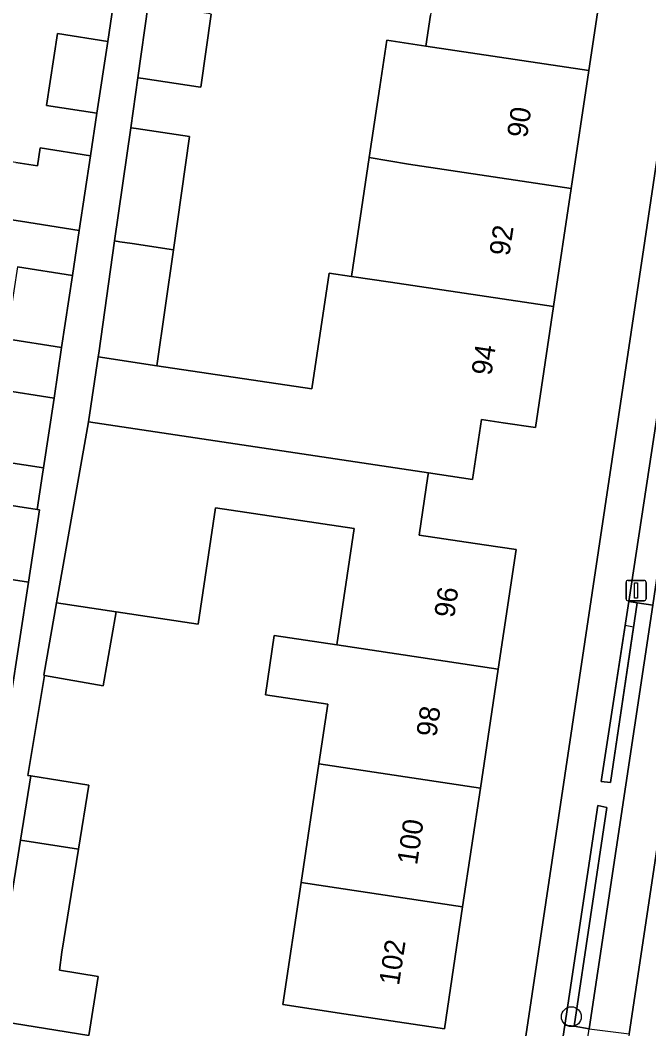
# Model space of a CAD drawing. Extents: x 163008 to 163854, y 382777 to 383982.
# Drawn here: x 163310.89 to 163341.84, y 383111.34 to 383160.98 of the extents above; entities that cross this region are included whole.
import ezdxf

# ---------------------------------------------------------------- set-up
doc = ezdxf.new("R2010")
doc.units = 0
for name, color, linetype in [('IMGEO_Boom', 7, 'Continuous'), ('IMGEO_Erf', 7, 'Continuous'), ('IMGEO_Groenvoorziening', 7, 'Continuous'), ('IMGEO_Haag', 7, 'Continuous'), ('IMGEO_Lichtmast', 7, 'Continuous'), ('IMGEO_Pand', 7, 'Continuous'), ('IMGEO_Pand_nummerreeks', 7, 'Continuous'), ('IMGEO_Parkeervlak_open', 7, 'Continuous'), ('IMGEO_Rijbaan_lokaal_gesloten', 7, 'Continuous'), ('IMGEO_Voetpad_open', 7, 'Continuous')]:
    doc.layers.add(name, color=color, linetype=linetype)

msp = doc.modelspace()

# ---------------------------------------------------------------- linework, layer by layer
at = {"layer": 'IMGEO_Boom'}
msp.add_circle((163338.027, 383111.934), 0.489, dxfattribs=at)
at = {"layer": 'IMGEO_Erf'}
for points in [[(163310.677, 383153.971), (163311.748, 383153.81), (163311.882, 383154.698), (163314.358, 383154.309), (163314.673, 383156.4), (163312.197, 383156.789), (163312.729, 383160.32), (163315.205, 383159.932), (163315.542, 383162.168), (163313.066, 383162.556), (163313.602, 383166.112), (163316.078, 383165.723), (163316.411, 383167.934), (163313.935, 383168.323), (163314.469, 383171.872), (163316.948, 383171.499), (163317.457, 383174.88), (163313.908, 383175.415), (163294.265, 383178.498)], [(163325.006, 383038.94), (163341.637, 383150.129), (163344.666, 383170.44)], [(163339.761, 383164.312), (163338.89, 383158.502), (163338.019, 383152.692), (163337.149, 383146.882), (163336.256, 383140.926), (163334.674, 383141.163), (163333.596, 383141.324), (163333.154, 383138.372), (163330.989, 383138.697), (163330.966, 383138.545), (163330.531, 383135.638), (163333.728, 383135.16), (163335.31, 383134.923), (163334.427, 383129.034), (163333.551, 383123.185), (163332.674, 383117.337), (163331.776, 383111.342), (163326.832, 383112.083), (163323.826, 383112.534), (163324.725, 383118.534), (163325.602, 383124.382), (163326.04, 383127.309), (163322.967, 383127.77), (163323.405, 383130.694), (163326.479, 383130.234), (163327.337, 383135.962), (163320.516, 383136.985), (163319.658, 383131.259), (163315.627, 383131.866), (163314.985, 383128.223), (163312.091, 383128.733), (163311.274, 383123.811), (163311.411, 383123.789), (163314.266, 383123.331), (163313.762, 383120.185), (163312.948, 383115.114), (163312.829, 383114.22), (163314.739, 383113.914), (163314.273, 383111.005), (163309.485, 383111.773)], [(163320.3, 383161.284), (163319.788, 383157.679), (163319.65, 383157.7), (163316.947, 383158.104), (163316.684, 383158.143), (163316.335, 383155.689), (163316.599, 383155.65), (163319.231, 383155.256), (163318.438, 383149.683), (163317.626, 383143.976), (163325.249, 383142.834), (163326.103, 383148.531), (163327.197, 383148.369), (163328.073, 383154.217), (163328.596, 383157.709), (163328.938, 383159.991), (163330.856, 383159.704), (163331.085, 383161.233)], [(163310.756, 383148.838), (163313.47, 383148.413), (163313.805, 383150.636), (163310.916, 383151.089), (163310.259, 383151.192)], [(163309.847, 383142.806), (163312.561, 383142.381), (163312.936, 383144.869), (163310.222, 383145.295)], [(163308.864, 383137.335), (163311.73, 383136.896), (163311.996, 383138.634), (163312.044, 383138.954), (163309.328, 383139.364)]]:
    msp.add_lwpolyline(points, dxfattribs=at)
at = {"layer": 'IMGEO_Groenvoorziening'}
for points in [[(163341.271, 383132.306), (163340.86, 383132.369), (163339.502, 383123.514), (163339.948, 383123.467)], [(163339.778, 383122.237), (163339.334, 383122.331), (163337.704, 383111.517), (163338.168, 383111.467)]]:
    msp.add_lwpolyline(points, close=True, dxfattribs=at)
at = {"layer": 'IMGEO_Haag'}
for points in [[(163341.091, 383131.106), (163340.678, 383131.182), (163339.502, 383123.514), (163339.948, 383123.467)], [(163339.778, 383122.237), (163339.334, 383122.331), (163337.704, 383111.517), (163338.168, 383111.467)]]:
    msp.add_lwpolyline(points, close=True, dxfattribs=at)
at = {"layer": 'IMGEO_Lichtmast'}
for p, q in [((163340.717, 383132.509), (163340.717, 383133.309)), ((163340.717, 383133.309), (163340.717, 383132.509)), ((163340.817, 383133.409), (163341.607, 383133.409)), ((163341.607, 383133.409), (163340.817, 383133.409)), ((163341.707, 383133.309), (163341.707, 383132.509)), ((163341.707, 383132.509), (163341.707, 383133.309)), ((163341.607, 383132.409), (163340.817, 383132.409)), ((163340.817, 383132.409), (163341.607, 383132.409))]:
    msp.add_line(p, q, dxfattribs=at)
msp.add_lwpolyline([(163341.137, 383133.284), (163341.287, 383133.284), (163341.287, 383132.534), (163341.137, 383132.534), (163341.137, 383133.284)], dxfattribs=at)
for centre, start, end in [((163340.817, 383133.309), 90, 180), ((163340.817, 383133.309), 90, 180), ((163341.607, 383133.309), 0, 90), ((163341.607, 383133.309), 360, 90), ((163340.817, 383132.509), 180, 270), ((163340.817, 383132.509), 180, 270), ((163341.607, 383132.509), 270, 0), ((163341.607, 383132.509), 270, 0)]:
    msp.add_arc(centre, 0.1, start, end, dxfattribs=at)
at = {"layer": 'IMGEO_Pand'}
for points in [[(163339.761, 383164.312), (163331.726, 383165.514), (163331.713, 383165.425), (163331.35, 383163), (163331.085, 383161.233), (163330.856, 383159.704), (163338.89, 383158.502)], [(163320.3, 383161.284), (163320.162, 383161.304), (163317.808, 383161.657), (163317.46, 383161.709), (163317.196, 383161.749), (163316.684, 383158.143), (163316.947, 383158.104), (163319.65, 383157.7), (163319.788, 383157.679)], [(163315.205, 383159.932), (163312.729, 383160.32), (163312.197, 383156.789), (163314.673, 383156.4)], [(163338.89, 383158.502), (163330.856, 383159.704), (163328.938, 383159.991), (163328.596, 383157.709), (163328.073, 383154.217), (163330.006, 383153.891), (163338.019, 383152.692)], [(163316.335, 383155.689), (163315.542, 383150.115), (163315.806, 383150.076), (163316.406, 383149.986), (163318.438, 383149.683), (163319.231, 383155.256), (163316.599, 383155.65)], [(163314.358, 383154.309), (163311.882, 383154.698), (163311.748, 383153.81), (163310.677, 383153.971), (163310.12, 383154.055), (163309.702, 383151.279), (163310.259, 383151.192), (163310.916, 383151.089), (163313.805, 383150.636)], [(163338.019, 383152.692), (163330.006, 383153.891), (163328.073, 383154.217), (163327.197, 383148.369), (163329.119, 383148.083), (163337.149, 383146.882)], [(163318.438, 383149.683), (163316.406, 383149.986), (163315.806, 383150.076), (163315.542, 383150.115), (163314.758, 383144.6), (163314.731, 383144.41), (163317.626, 383143.976)], [(163313.47, 383148.413), (163310.756, 383148.838), (163310.222, 383145.295), (163312.936, 383144.869)], [(163337.149, 383146.882), (163329.119, 383148.083), (163327.197, 383148.369), (163326.103, 383148.531), (163325.249, 383142.834), (163317.626, 383143.976), (163314.731, 383144.41), (163314.252, 383141.206), (163330.989, 383138.697), (163333.154, 383138.372), (163333.596, 383141.324), (163334.674, 383141.163), (163336.256, 383140.926)], [(163312.561, 383142.381), (163309.847, 383142.806), (163309.328, 383139.364), (163312.044, 383138.954)], [(163335.31, 383134.923), (163333.728, 383135.16), (163330.531, 383135.638), (163330.966, 383138.545), (163330.989, 383138.697), (163314.252, 383141.206), (163312.685, 383132.309), (163315.627, 383131.866), (163319.658, 383131.259), (163320.516, 383136.985), (163327.337, 383135.962), (163326.479, 383130.234), (163334.427, 383129.034)], [(163311.85, 383136.878), (163311.73, 383136.896), (163308.864, 383137.335), (163308.322, 383133.786), (163311.306, 383133.318)], [(163308.322, 383133.786), (163307.44, 383128.018), (163310.425, 383127.55), (163311.306, 383133.318)], [(163315.627, 383131.866), (163312.685, 383132.309), (163312.056, 383128.739), (163312.091, 383128.733), (163314.985, 383128.223)], [(163325.602, 383124.382), (163333.551, 383123.185), (163334.427, 383129.034), (163326.479, 383130.234), (163323.405, 383130.694), (163322.967, 383127.77), (163326.04, 383127.309)], [(163325.602, 383124.382), (163324.725, 383118.534), (163332.674, 383117.337), (163333.551, 383123.185)], [(163311.411, 383123.789), (163310.902, 383120.616), (163313.762, 383120.185), (163314.266, 383123.331)], [(163313.762, 383120.185), (163310.902, 383120.616), (163309.485, 383111.773), (163314.273, 383111.005), (163314.739, 383113.914), (163312.829, 383114.22), (163312.948, 383115.114)], [(163332.674, 383117.337), (163324.725, 383118.534), (163323.826, 383112.534), (163326.832, 383112.083), (163331.776, 383111.342)]]:
    msp.add_lwpolyline(points, close=True, dxfattribs=at)
at = {"layer": 'IMGEO_Parkeervlak_open'}
for points in [[(163359.594, 383237.191), (163353.206, 383238.156), (163353.059, 383236.624), (163354.474, 383236.052), (163353.959, 383232.549), (163352.699, 383224.192), (163350.745, 383211.225), (163350.535, 383209.802), (163350.513, 383209.655), (163344.964, 383172.44), (163344.666, 383170.44), (163341.637, 383150.129), (163325.006, 383038.94), (163324.506, 383036.205), (163323.355, 383028.546), (163322.78, 383023.472), (163322.281, 383020.078), (163327.116, 383019.173), (163327.994, 383024.746), (163328.1, 383025.321)], [(163336.468, 383103.432), (163337.704, 383111.517), (163339.334, 383122.331), (163339.778, 383122.237), (163338.168, 383111.467), (163338.907, 383111.332), (163342.03, 383132.19), (163341.271, 383132.306), (163339.948, 383123.467), (163339.502, 383123.514), (163340.86, 383132.369), (163342.226, 383141.307), (163343.153, 383147.538)]]:
    msp.add_lwpolyline(points, dxfattribs=at)
msp.add_lwpolyline([(163338.907, 383111.332), (163340.877, 383111.094), (163346.155, 383146.302), (163346.845, 383150.922), (163349.786, 383170.627), (163347.799, 383170.932), (163344.647, 383149.662), (163343.37, 383141.133), (163342.03, 383132.19)], close=True, dxfattribs=at)
at = {"layer": 'IMGEO_Rijbaan_lokaal_gesloten'}
msp.add_lwpolyline([(163333.064, 383024.594), (163351.16, 383145.514), (163346.155, 383146.302), (163340.877, 383111.094), (163339.666, 383103.012), (163335.675, 383076.387), (163334.357, 383067.599), (163328.173, 383025.814), (163328.1, 383025.321)], close=True, dxfattribs=at)
at = {"layer": 'IMGEO_Voetpad_open'}
for points in [[(163294.265, 383178.498), (163313.908, 383175.415), (163317.457, 383174.88), (163316.948, 383171.499), (163316.411, 383167.934), (163316.078, 383165.723), (163315.542, 383162.168), (163315.205, 383159.932), (163314.673, 383156.4), (163314.358, 383154.309), (163313.805, 383150.636), (163313.47, 383148.413), (163312.936, 383144.869), (163312.561, 383142.381), (163312.044, 383138.954), (163311.996, 383138.634), (163311.73, 383136.896), (163311.85, 383136.878), (163311.306, 383133.318), (163310.425, 383127.55)], [(163309.485, 383111.773), (163310.902, 383120.616), (163311.411, 383123.789), (163311.274, 383123.811), (163312.091, 383128.733), (163312.056, 383128.739), (163312.685, 383132.309), (163314.252, 383141.206), (163314.731, 383144.41), (163314.758, 383144.6), (163315.542, 383150.115), (163316.335, 383155.689), (163316.684, 383158.143), (163317.196, 383161.749)]]:
    msp.add_lwpolyline(points, dxfattribs=at)
for points in [[(163343.37, 383141.133), (163342.623, 383141.247), (163342.226, 383141.307), (163340.86, 383132.369), (163341.271, 383132.306), (163342.03, 383132.19)], [(163337.702, 383103.259), (163338.907, 383111.332), (163338.168, 383111.467), (163337.704, 383111.517), (163336.468, 383103.432), (163336.93, 383103.375)]]:
    msp.add_lwpolyline(points, close=True, dxfattribs=at)

# ---------------------------------------------------------------- texts
at = {"layer": 'IMGEO_Pand_nummerreeks'}
for s, rotation, p in [('90', 81.4746, (163335.841, 383155.156)), ('92', 81.4746, (163334.969, 383149.34)), ('94', 81.4746, (163334.088, 383143.46)), ('96', 81.4746, (163332.255, 383131.534)), ('98', 81.4767, (163331.375, 383125.668)), ('100', 81.4767, (163330.43, 383119.366)), ('102', 81.4767, (163329.541, 383113.438))]:
    msp.add_text(s, height=1, rotation=rotation, dxfattribs=at).set_placement(p)

doc.saveas('drawing.dxf')
